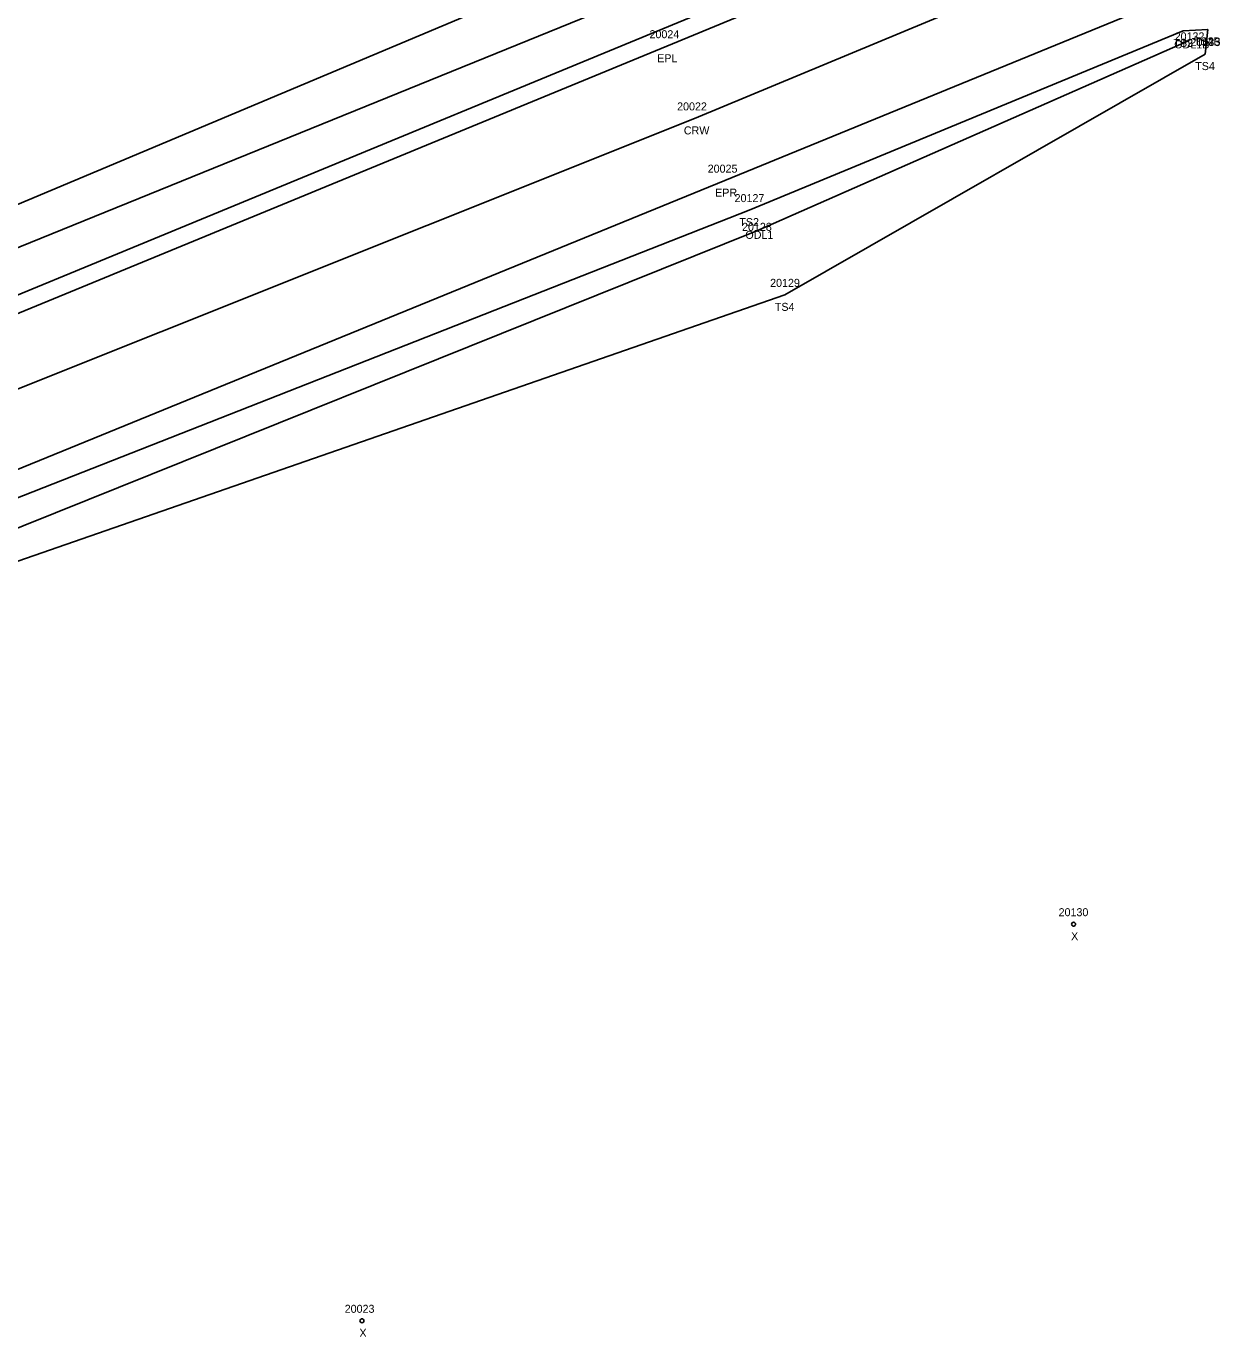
# Model space of a CAD drawing. Extents: x 1966740 to 1969291, y 1117378 to 1118461.
# Drawn here: x 1966891.2 to 1967041.9, y 1117377.7 to 1117541.5 of the extents above; entities that cross this region are included whole.
import ezdxf

# ---------------------------------------------------------------- set-up
doc = ezdxf.new("R2010")
doc.units = 0
for name, color, linetype in [('RD_DTM_BkLn1', 7, 'Continuous'), ('RD_DTM_BkLn2', 7, 'Continuous'), ('RD_EX_H2O', 7, 'Continuous'), ('RD_EX_H2O_txCode', 7, 'Continuous'), ('RD_EX_Road', 7, 'Continuous'), ('RD_EX_Road_txCode', 7, 'Continuous'), ('RD_SMD_Locator', 7, 'Continuous'), ('RD_SMD_Misc', 7, 'Continuous')]:
    doc.layers.add(name, color=color, linetype=linetype)

msp = doc.modelspace()

# ---------------------------------------------------------------- linework, layer by layer
at = {"layer": 'RD_DTM_BkLn1'}
msp.add_lwpolyline([(1966772.57, 1117449.88), (1966874.49, 1117489.87), (1966974.64, 1117529.93), (1967075.06, 1117571.68), (1967175.91, 1117613.34), (1967274.11, 1117653.69), (1967325.25, 1117674.8), (1967374.73, 1117695), (1967473.9, 1117733.1), (1967569.8, 1117771.9), (1967665.19, 1117809.79), (1967697.89, 1117822.8)], dxfattribs=at)
at = {"layer": 'RD_DTM_BkLn2'}
for points in [[(1966768.15, 1117461.43), (1966869.41, 1117499.34), (1967070.52, 1117582.35), (1967171.25, 1117624.02), (1967269.74, 1117664.9), (1967320.21, 1117685.71), (1967369.37, 1117708.48), (1967468.51, 1117746.66), (1967564.6, 1117784.47), (1967654.68, 1117828.05), (1967680.1, 1117841.48), (1967687.91, 1117842.93), (1967691.45, 1117838.71), (1967693.03, 1117834.22)], [(1966766.42, 1117472.19), (1966865.47, 1117508.82), (1967066.64, 1117593.45), (1967166.55, 1117636.11), (1967264.62, 1117677.56), (1967315.66, 1117698.57), (1967367.9, 1117716.34), (1967464.92, 1117753.87), (1967560.73, 1117793.63)], [(1966786.01, 1117438.62), (1966877.32, 1117477.51), (1966981.49, 1117518.47), (1967035.72, 1117540.87), (1967038.77, 1117541.05)], [(1966789.47, 1117432.06), (1966880.12, 1117471.13), (1966985.94, 1117507.88), (1967038.45, 1117537.97), (1967038.77, 1117541.05)]]:
    msp.add_lwpolyline(points, dxfattribs=at)
at = {"layer": 'RD_EX_H2O'}
for points in [[(1966766.64, 1117466.58), (1966867.24, 1117504.5), (1967068.76, 1117586.41), (1967167.95, 1117632.67), (1967266.82, 1117671.88), (1967316.79, 1117693.47), (1967368.01, 1117713.34), (1967465.67, 1117751.74), (1967560.73, 1117793.63)], [(1966787.6, 1117435.18), (1966878.84, 1117474.24), (1966982.42, 1117515.88), (1967036.47, 1117539.68)]]:
    msp.add_lwpolyline(points, dxfattribs=at)
at = {"layer": 'RD_EX_Road'}
for points in [[(1966769.51, 1117457.48), (1966870.16, 1117497.34), (1966971.19, 1117538.95), (1967071.09, 1117580.24), (1967172.6, 1117621.53), (1967270.79, 1117661.66), (1967321.12, 1117682.57), (1967371.52, 1117702.88), (1967470.26, 1117741.55), (1967566.67, 1117779.5), (1967661.25, 1117817.53), (1967694.4, 1117831.19), (1967697.89, 1117822.8)], [(1966775.75, 1117440.57), (1966876.18, 1117480.39), (1966978.46, 1117522.15), (1967078.26, 1117563.06), (1967180.7, 1117605.06), (1967277.98, 1117644.72), (1967308.82, 1117656.67)]]:
    msp.add_lwpolyline(points, dxfattribs=at)
at = {"layer": 'RD_SMD_Locator'}
for centre, radius in [((1967035.72, 1117540.87), 0.001), ((1967038.77, 1117541.05), 0.001), ((1967038.77, 1117541.05), 0.001), ((1966971.19, 1117538.95), 0.001), ((1967036.47, 1117539.68), 0.001), ((1967038.45, 1117537.97), 0.001), ((1966974.64, 1117529.93), 0.001), ((1966978.46, 1117522.15), 0.001), ((1966981.49, 1117518.47), 0.001), ((1966982.42, 1117515.88), 0.001), ((1966985.94, 1117507.88), 0.001), ((1967022.01, 1117429.23), 0.25), ((1966933.11, 1117379.67), 0.25)]:
    msp.add_circle(centre, radius, dxfattribs=at)

# ---------------------------------------------------------------- texts
at = {"layer": 'RD_EX_H2O_txCode'}
for s, p in [('20132', (1967034.64, 1117539.68)), ('ODL1B', (1967034.59, 1117538.68)), ('20128', (1966980.59, 1117515.88)), ('ODL1', (1966981.01, 1117514.88))]:
    msp.add_text(s, height=1, dxfattribs=at).set_placement(p)
at = {"layer": 'RD_EX_Road_txCode'}
for s, p in [('20024', (1966969.03, 1117539.95)), ('EPL', (1966969.99, 1117536.95)), ('20025', (1966976.3, 1117523.15)), ('EPR', (1966977.23, 1117520.15))]:
    msp.add_text(s, height=1, dxfattribs=at).set_placement(p)
at = {"layer": 'RD_SMD_Misc'}
for s, p in [('TS2', (1967034.48, 1117538.87)), ('20133', (1967036.62, 1117538.97)), ('TS4B', (1967037.05, 1117539.05)), ('TS2B', (1967037.05, 1117539.05)), ('TS4', (1967037.21, 1117535.97)), ('20022', (1966972.48, 1117530.93)), ('CRW', (1966973.32, 1117527.93)), ('20127', (1966979.66, 1117519.47)), ('TS2', (1966980.25, 1117516.47)), ('20129', (1966984.1, 1117508.88)), ('TS4', (1966984.69, 1117505.88)), ('20130', (1967020.14, 1117430.23)), ('X', (1967021.7, 1117427.23)), ('20023', (1966930.95, 1117380.67)), ('X', (1966932.79, 1117377.67))]:
    msp.add_text(s, height=1, dxfattribs=at).set_placement(p)

doc.saveas('drawing.dxf')
